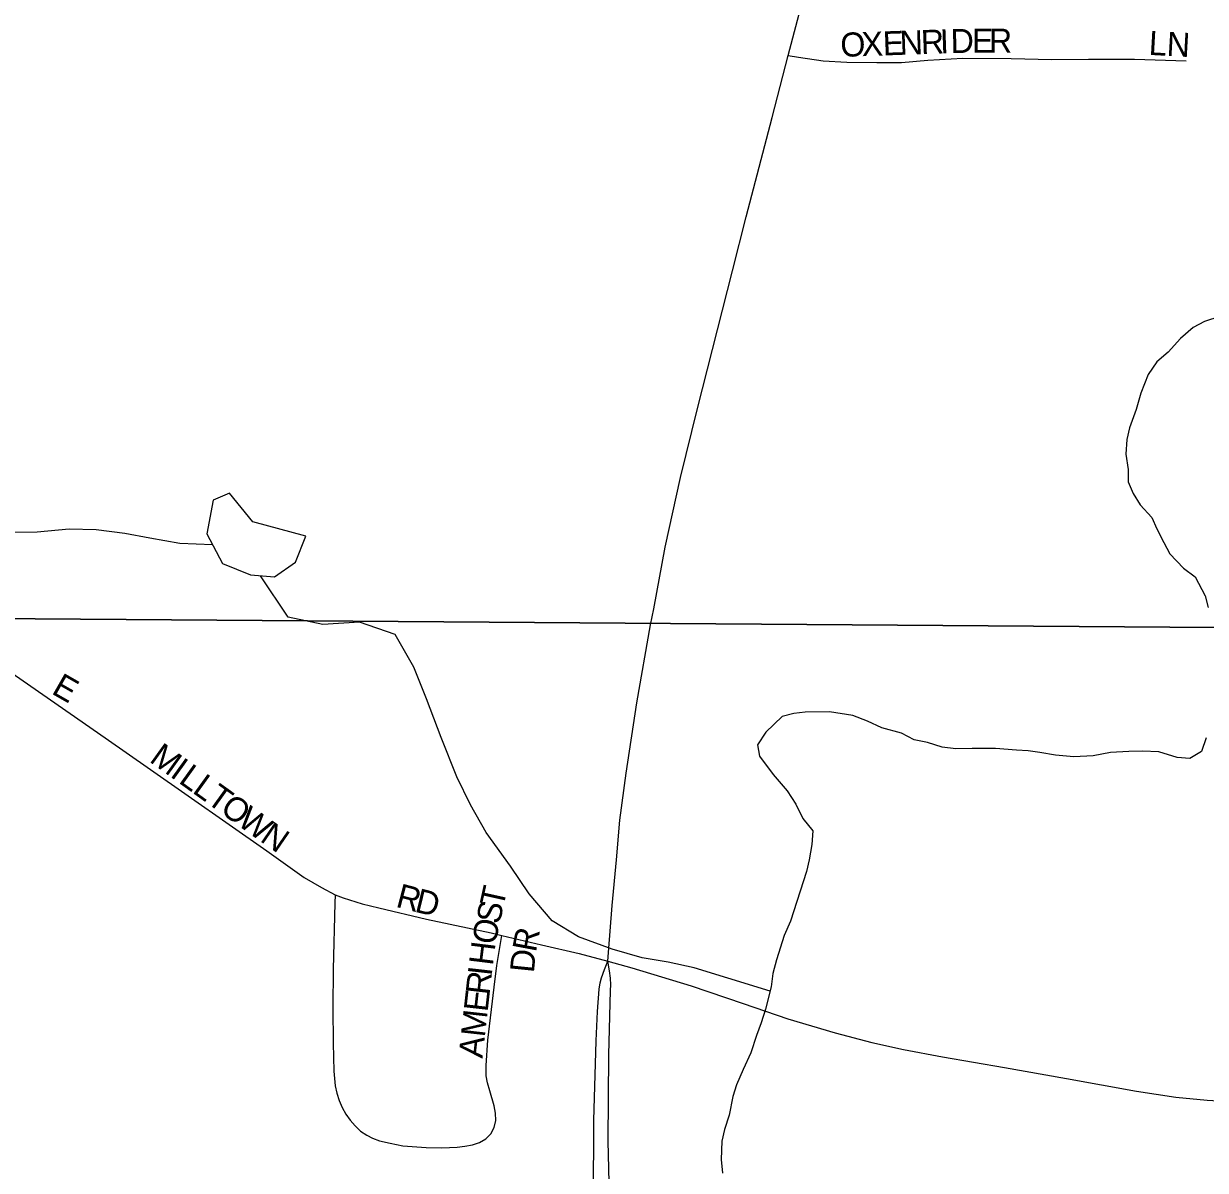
# Model space of a CAD drawing. Extents: x 1985906 to 2360102, y 891258 to 1222054.
# Drawn here: x 2125185 to 2127638, y 1035026 to 1037407 of the extents above; entities that cross this region are included whole.
import ezdxf

# ---------------------------------------------------------------- set-up
doc = ezdxf.new("R2010")
doc.units = 0
for name, color, linetype in [('GM_X_City_Street', 7, 'Continuous'), ('GM_X_City_Street_Text', 7, 'Continuous'), ('GM_X_Minor_Lake', 7, 'Continuous'), ('GM_X_Minor_River', 7, 'Continuous'), ('GM_X_Section', 7, 'Continuous'), ('GM_X_State_Route', 7, 'Continuous')]:
    doc.layers.add(name, color=color, linetype=linetype)

msp = doc.modelspace()

# ---------------------------------------------------------------- linework, layer by layer
at = {"layer": 'GM_X_City_Street'}
for points in [[(2126772.2, 1037341.1), (2126793.5, 1037337.9), (2126844.8, 1037330), (2126893.5, 1037327.1), (2126955.8, 1037326.8), (2127007.1, 1037326.8), (2127062.1, 1037331.4), (2127134.5, 1037335.9), (2127235.3, 1037335), (2127319.7, 1037333.1), (2127395.7, 1037334), (2127491.1, 1037334), (2127598.3, 1037330.3)], [(2125026.6, 1036146.4), (2125062.1, 1036126.3), (2125152, 1036064.4), (2125353.5, 1035923.9), (2125447.7, 1035858.4), (2125689.3, 1035689.4), (2125767.3, 1035634.1), (2125803.2, 1035613), (2125831.6, 1035598.3)], [(2125831.6, 1035598.3), (2125830.8, 1035580.8), (2125827, 1035443.9), (2125826.4, 1035363.3), (2125827, 1035289.6), (2125828.8, 1035231.7), (2125831.3, 1035201.6), (2125834.8, 1035186.2), (2125839.6, 1035171.1), (2125845.8, 1035156.6), (2125853.4, 1035142.8), (2125862.4, 1035129.8), (2125872.7, 1035117.9), (2125884.2, 1035107.4), (2125896.9, 1035098.5), (2125908.7, 1035092.9), (2125923.4, 1035087.4), (2125945.5, 1035081.9), (2125972, 1035076.9), (2126020.6, 1035073.2), (2126052.8, 1035072.4), (2126084.9, 1035073.8), (2126100.8, 1035075.7), (2126116.3, 1035078.8), (2126130.8, 1035083.8), (2126143.9, 1035091.4), (2126154.6, 1035101.8), (2126161.8, 1035114.7), (2126164.8, 1035129.2), (2126164.5, 1035144.4), (2126161.2, 1035159.6), (2126152.4, 1035191.2), (2126147.6, 1035207.7), (2126144.9, 1035222.4), (2126144.9, 1035243.6), (2126148.6, 1035295.9), (2126161.5, 1035406.2), (2126167, 1035451.2), (2126174.3, 1035492.5), (2126177.7, 1035513.8)], [(2125831.6, 1035598.3), (2125848.2, 1035591.8), (2125887.7, 1035579), (2125922.3, 1035570.9), (2126020.9, 1035547.7), (2126155, 1035519.2), (2126177.7, 1035513.8)], [(2126177.7, 1035513.8), (2126259.8, 1035494.4), (2126337.9, 1035475.9), (2126397.4, 1035460)], [(2126397.4, 1035460), (2126447.2, 1035446.6), (2126570.3, 1035408.8), (2126678.7, 1035372.1), (2126771.5, 1035340.8), (2126869.8, 1035311.4), (2126946, 1035291.2), (2127011.7, 1035277.1), (2127092.1, 1035261.4), (2127221.3, 1035239.3), (2127350.2, 1035216.2), (2127495.4, 1035189.9), (2127576.7, 1035178), (2127642.1, 1035171.3), (2127724.2, 1035166.8), (2127779.5, 1035165.6)]]:
    msp.add_lwpolyline(points, dxfattribs=at)
at = {"layer": 'GM_X_Minor_Lake'}
for points in [[(2125660.6, 1036372.5), (2125612.2, 1036432.3), (2125578.3, 1036418), (2125564.8, 1036347.8), (2125597.2, 1036286), (2125655.4, 1036262.4), (2125705.4, 1036258.8), (2125749.2, 1036289.1), (2125770.8, 1036343.3)], [(2125770.8, 1036343.3), (2125660.6, 1036372.5)]]:
    msp.add_lwpolyline(points, dxfattribs=at)
at = {"layer": 'GM_X_Minor_River'}
for points in [[(2127668.5, 1036799), (2127636.5, 1036788.5), (2127612.6, 1036776.2), (2127586.8, 1036753.8), (2127561, 1036725.3), (2127537.2, 1036705), (2127519.5, 1036678.7), (2127503.9, 1036640.3), (2127494.3, 1036606.1), (2127480.7, 1036567.8), (2127475, 1036543.7), (2127473.4, 1036513.6), (2127477.8, 1036481.5), (2127478.2, 1036455.5), (2127488.5, 1036431.5), (2127502.9, 1036407.7), (2127527.3, 1036381.9), (2127537.7, 1036358), (2127552.1, 1036330.1), (2127564.4, 1036306.2), (2127592.9, 1036276.5), (2127617.3, 1036258.7), (2127637.9, 1036218.9), (2127644.2, 1036194.9)], [(2125576.6, 1036325.3), (2125509, 1036327.4), (2125446.9, 1036338.9), (2125394.8, 1036348.5), (2125334.8, 1036356.1), (2125278.8, 1036357.7), (2125212.8, 1036351.2), (2125156.8, 1036350.8), (2125098.8, 1036362.3), (2125048.6, 1036388), (2124943.4, 1036442.1)], [(2126734.5, 1035397.8), (2126647, 1035424.8), (2126576.9, 1035446.3), (2126522.8, 1035457.9), (2126468.8, 1035467.5), (2126406.6, 1035485), (2126336.5, 1035510.5), (2126282.3, 1035544.2), (2126233.9, 1035599.9), (2126195.5, 1035657.7), (2126145, 1035727.4), (2126112.6, 1035785.2), (2126084.2, 1035843.1), (2126051.7, 1035924.9), (2126021.1, 1036004.8), (2125994.7, 1036070.7), (2125956.2, 1036138.5), (2125882, 1036164), (2125806.1, 1036159.4), (2125734, 1036174.9), (2125676.3, 1036260.9)], [(2127639.7, 1035924.1), (2127630, 1035895.9), (2127606.1, 1035881.5), (2127580, 1035883.2), (2127541.7, 1035894.7), (2127507.5, 1035896.2), (2127479.4, 1035895.9), (2127441.3, 1035893.3), (2127405.2, 1035886.8), (2127365.1, 1035884.3), (2127326.9, 1035887.8), (2127294.7, 1035893.4), (2127270.5, 1035897.1), (2127246.4, 1035898.8), (2127202.2, 1035902.2), (2127178.1, 1035901.9), (2127154, 1035901.6), (2127119.9, 1035901.1), (2127091.7, 1035904.8), (2127061.5, 1035914.4), (2127033.3, 1035920), (2127007, 1035933.7), (2126966.7, 1035945.2), (2126936.4, 1035958.8), (2126906.1, 1035970.5), (2126857.8, 1035977.8), (2126807.6, 1035977.2), (2126783.5, 1035974.9), (2126759.5, 1035968.5), (2126725.8, 1035936), (2126708.1, 1035909.7), (2126712.4, 1035885.7), (2126741, 1035847.9), (2126769.6, 1035814.2), (2126788, 1035786.4), (2126802.4, 1035756.5), (2126822.9, 1035730.7), (2126821.2, 1035702.6), (2126815.6, 1035670.4), (2126809.9, 1035646.3), (2126777.1, 1035543.5), (2126763.4, 1035513.3), (2126748, 1035462.9), (2126740.3, 1035434.7), (2126736.7, 1035406.6), (2126725.2, 1035360.3), (2126715.6, 1035332.1), (2126705.9, 1035305.9), (2126694.3, 1035269.7), (2126678.7, 1035235.3)], [(2126678.7, 1035235.3), (2126665, 1035203.1), (2126657.3, 1035178.9), (2126649.8, 1035140.7), (2126640.1, 1035110.5), (2126634.4, 1035086.3), (2126632.9, 1035048.2), (2126635.3, 1035020.1)]]:
    msp.add_lwpolyline(points, dxfattribs=at)
at = {"layer": 'GM_X_Section'}
for points in [[(2124934, 1041489.3), (2130109.5, 1041463.5), (2130202.8, 1036134.8), (2125019.2, 1036172.5)], [(2125019.2, 1036172.5), (2130202.8, 1036134.8), (2130280.1, 1030804), (2125066.6, 1030831.6)]]:
    msp.add_lwpolyline(points, close=True, dxfattribs=at)
at = {"layer": 'GM_X_State_Route'}
for points in [[(2126492.8, 1036192.3), (2126516.9, 1036320.1), (2126548.5, 1036464.5), (2126583.4, 1036608.2), (2126656.5, 1036893.9), (2126685.1, 1037005.9), (2126738.7, 1037212.6), (2126772.2, 1037341.1), (2126829.9, 1037562.3)], [(2126397.4, 1035460), (2126398.8, 1035478.5), (2126406.7, 1035575.7), (2126415.2, 1035670.9), (2126422.7, 1035752.9), (2126435.3, 1035850.8), (2126457.9, 1035996.9), (2126486.4, 1036158.7), (2126492.8, 1036192.3)], [(2126387.6, 1034506.6), (2126372.4, 1034748.5), (2126368.8, 1034847.8), (2126368, 1034963.7), (2126368.5, 1035129.2), (2126373, 1035294.8), (2126376.3, 1035355.6), (2126379.7, 1035402.2), (2126381.8, 1035415.1), (2126384.5, 1035425.4), (2126390.6, 1035442.9), (2126397.4, 1035460)], [(2126403, 1034936.3), (2126401.3, 1034971.8), (2126398.5, 1035086.3), (2126399.3, 1035266), (2126403.2, 1035399.3), (2126403.5, 1035411.4), (2126403, 1035424.9), (2126401.1, 1035440), (2126397.4, 1035460)]]:
    msp.add_lwpolyline(points, dxfattribs=at)

# ---------------------------------------------------------------- texts
at = {"layer": 'GM_X_City_Street_Text'}
for s, rotation, p in [('O', 1.9674, (2126881.2, 1037338.3)), ('X', 1.9763, (2126925.2, 1037339.8)), ('E', 1.9674, (2126969.2, 1037341.3)), ('N', 1.9456, (2127004.3, 1037342.5)), ('R', 1.9768, (2127048.3, 1037344)), ('I', 1.9958, (2127087.9, 1037345.4)), ('D', 1.1803, (2127109.7, 1037346.1)), ('E', 0.082, (2127153.5, 1037347)), ('R', 0, (2127188.7, 1037347.1)), ('LN', 356.8215, (2127519.8, 1037342.7)), ('E', 330.2686, (2125240.4, 1036017)), ('M', 324.2887, (2125443.6, 1035875.7)), ('I', 324.2886, (2125486.5, 1035844.9)), ('L', 324.294, (2125504.3, 1035832.1)), ('L', 324.2559, (2125532.9, 1035811.5)), ('T', 324.315, (2125561.5, 1035790.9)), ('O', 324.2667, (2125590.1, 1035770.4)), ('W', 324.2928, (2125625.8, 1035744.7)), ('N', 325.5036, (2125673.2, 1035710.6)), ('R', 345.2923, (2125955.4, 1035573.6)), ('D', 346.3364, (2125994.6, 1035563.3)), ('T', 77.4682, (2126180.1, 1035569.7)), ('S', 77.4949, (2126172.5, 1035535.4)), ('O', 78.7586, (2126163.9, 1035492.5)), ('R', 79.3759, (2126248.1, 1035477.4)), ('H', 82.8994, (2126158.7, 1035449.8)), ('D', 84.285, (2126243.9, 1035434.8)), ('R', 83.6249, (2126151.8, 1035388.7)), ('I', 83.6067, (2126156.2, 1035428.1)), ('E', 83.6379, (2126147.9, 1035353.7)), ('M', 83.6115, (2126142, 1035301.2)), ('A', 83.626, (2126137.2, 1035257.5))]:
    msp.add_text(s, height=50, rotation=rotation, dxfattribs=at).set_placement(p)

doc.saveas('drawing.dxf')
